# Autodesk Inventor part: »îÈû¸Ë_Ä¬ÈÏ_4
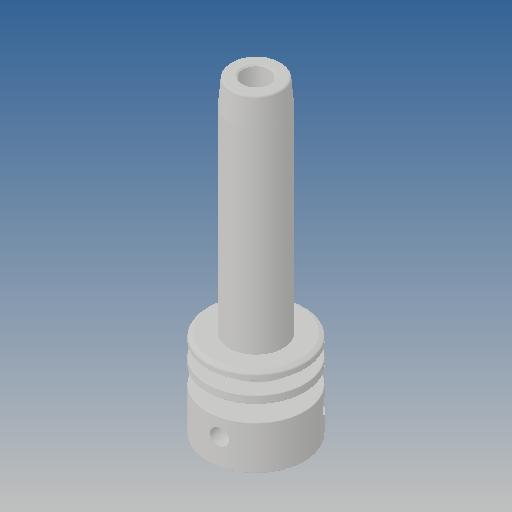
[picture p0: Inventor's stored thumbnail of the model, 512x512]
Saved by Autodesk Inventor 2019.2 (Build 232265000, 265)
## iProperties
Created: 2013-03
Part Number: »îÈû¸Ë_Ä¬ÈÏ_4
Material: Ogólny
Document SubType Name: Modeling
Designer: CADENGINEERING4
Density: 1 g/cm^3
Appearance: Domyślna
Author: CADENGINEERING4
Revision Number: ÈÎºÎ
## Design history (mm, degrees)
feature "NONE"
node "Bryła1"
